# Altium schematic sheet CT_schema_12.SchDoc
size 209 x 185 mm
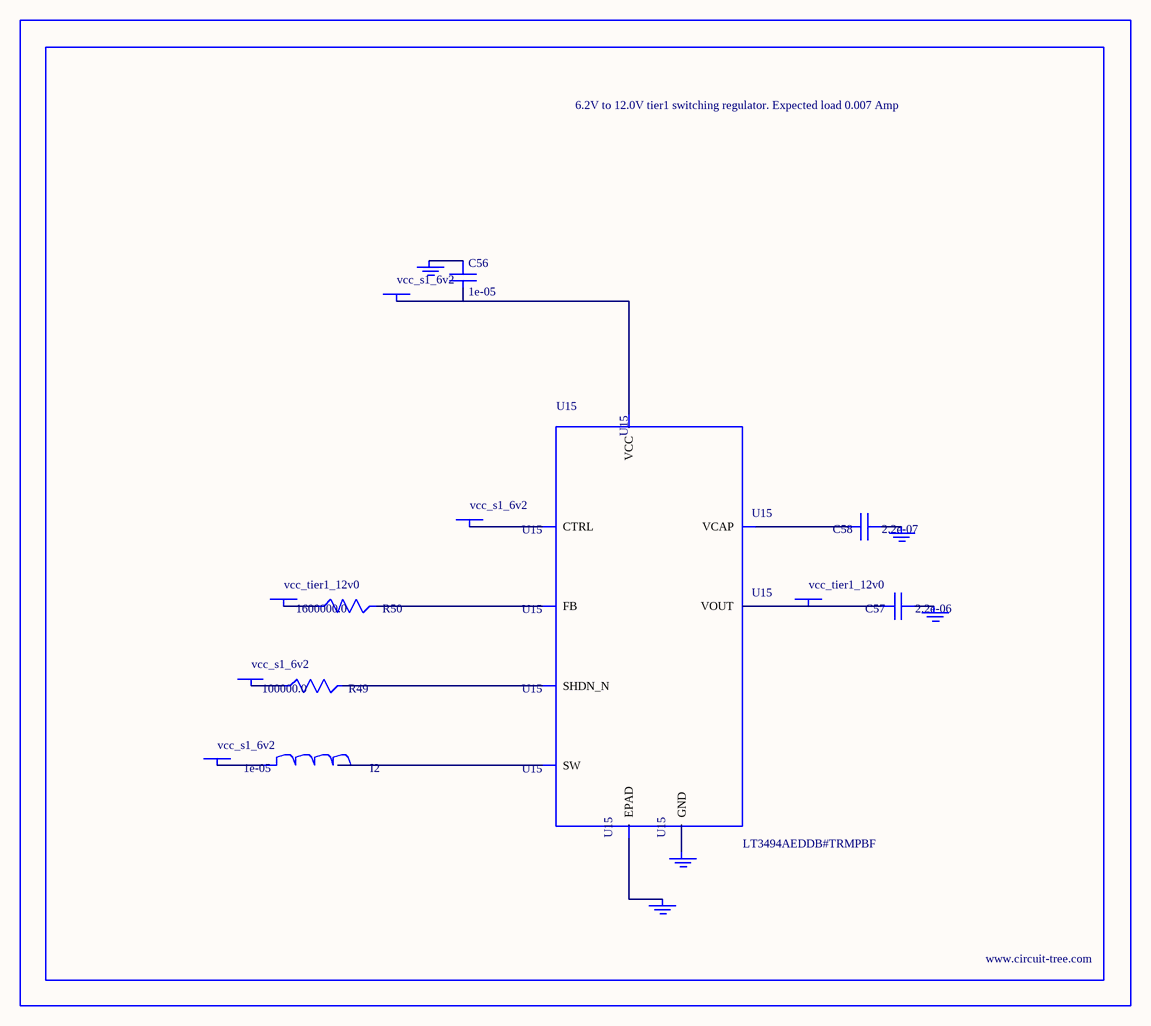
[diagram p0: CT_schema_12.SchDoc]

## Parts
BORDER11  (no value)
C56  1e-05  [C1210]
C57  2.2e-06  [C0603]
C58  2.2e-07  [C0603]
GND_INSTANCE_11_0  (no value)
GND_INSTANCE_11_1  (no value)
GND_INSTANCE_11_2  (no value)
GND_INSTANCE_11_3  (no value)
GND_INSTANCE_11_4  (no value)
I2  1e-05  [L1210]
POWER_INSTANCE_11_0  vcc_s1_6v2
POWER_INSTANCE_11_1  vcc_s1_6v2
POWER_INSTANCE_11_2  vcc_s1_6v2
POWER_INSTANCE_11_3  vcc_s1_6v2
POWER_INSTANCE_11_4  vcc_tier1_12v0
POWER_INSTANCE_11_5  vcc_tier1_12v0
R49  100000.0  [R0603]
R50  1600000.0  [R0603]
U15  LT3494AEDDB#TRMPBF  [DFN-8_DDB]

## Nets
NetC56_1: C56.1 GND_INSTANCE_11_0.0(GND)
NetC56_2: C56.2 POWER_INSTANCE_11_1.0(PWR) U15.3(VCC)
NetC57_1: C57.1 GND_INSTANCE_11_1.0(GND)
NetC57_2: C57.2 POWER_INSTANCE_11_5.0(PWR) U15.7(VOUT)
NetC58_1: C58.1 GND_INSTANCE_11_2.0(GND)
NetC58_2: C58.2 U15.8(VCAP)
NetGND_INSTANCE_11_3_0: GND_INSTANCE_11_3.0(GND) U15.9(EPAD)
NetGND_INSTANCE_11_4_0: GND_INSTANCE_11_4.0(GND) U15.2(GND)
NetI2_1: I2.1 POWER_INSTANCE_11_0.0(PWR)
NetI2_2: I2.2 U15.1(SW)
NetPOWER_INSTANCE_11_2_0: POWER_INSTANCE_11_2.0(PWR) U15.4(CTRL)
NetPOWER_INSTANCE_11_3_0: POWER_INSTANCE_11_3.0(PWR) R49.1
NetPOWER_INSTANCE_11_4_0: POWER_INSTANCE_11_4.0(PWR) R50.1
NetR49_2: R49.2 U15.5(SHDN_N)
NetR50_2: R50.2 U15.6(FB)

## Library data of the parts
BORDER11 = BORDER_PAGE11
C56 = C1210C106K5PACTU
C57 = GRM188R61H225KE1115D
C58 = C0603C224K3RAC
GND_INSTANCE_11_0-GND_INSTANCE_11_4 = GND
I2 = CBC3225T100MR
POWER_INSTANCE_11_0-POWER_INSTANCE_11_5 = PWR
R49 = RC0603JR-07100KL
R50 = RC0603JR-071M6L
